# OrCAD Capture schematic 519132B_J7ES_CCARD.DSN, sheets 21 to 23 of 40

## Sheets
21 21.POWER LM5176: size C; rev: A
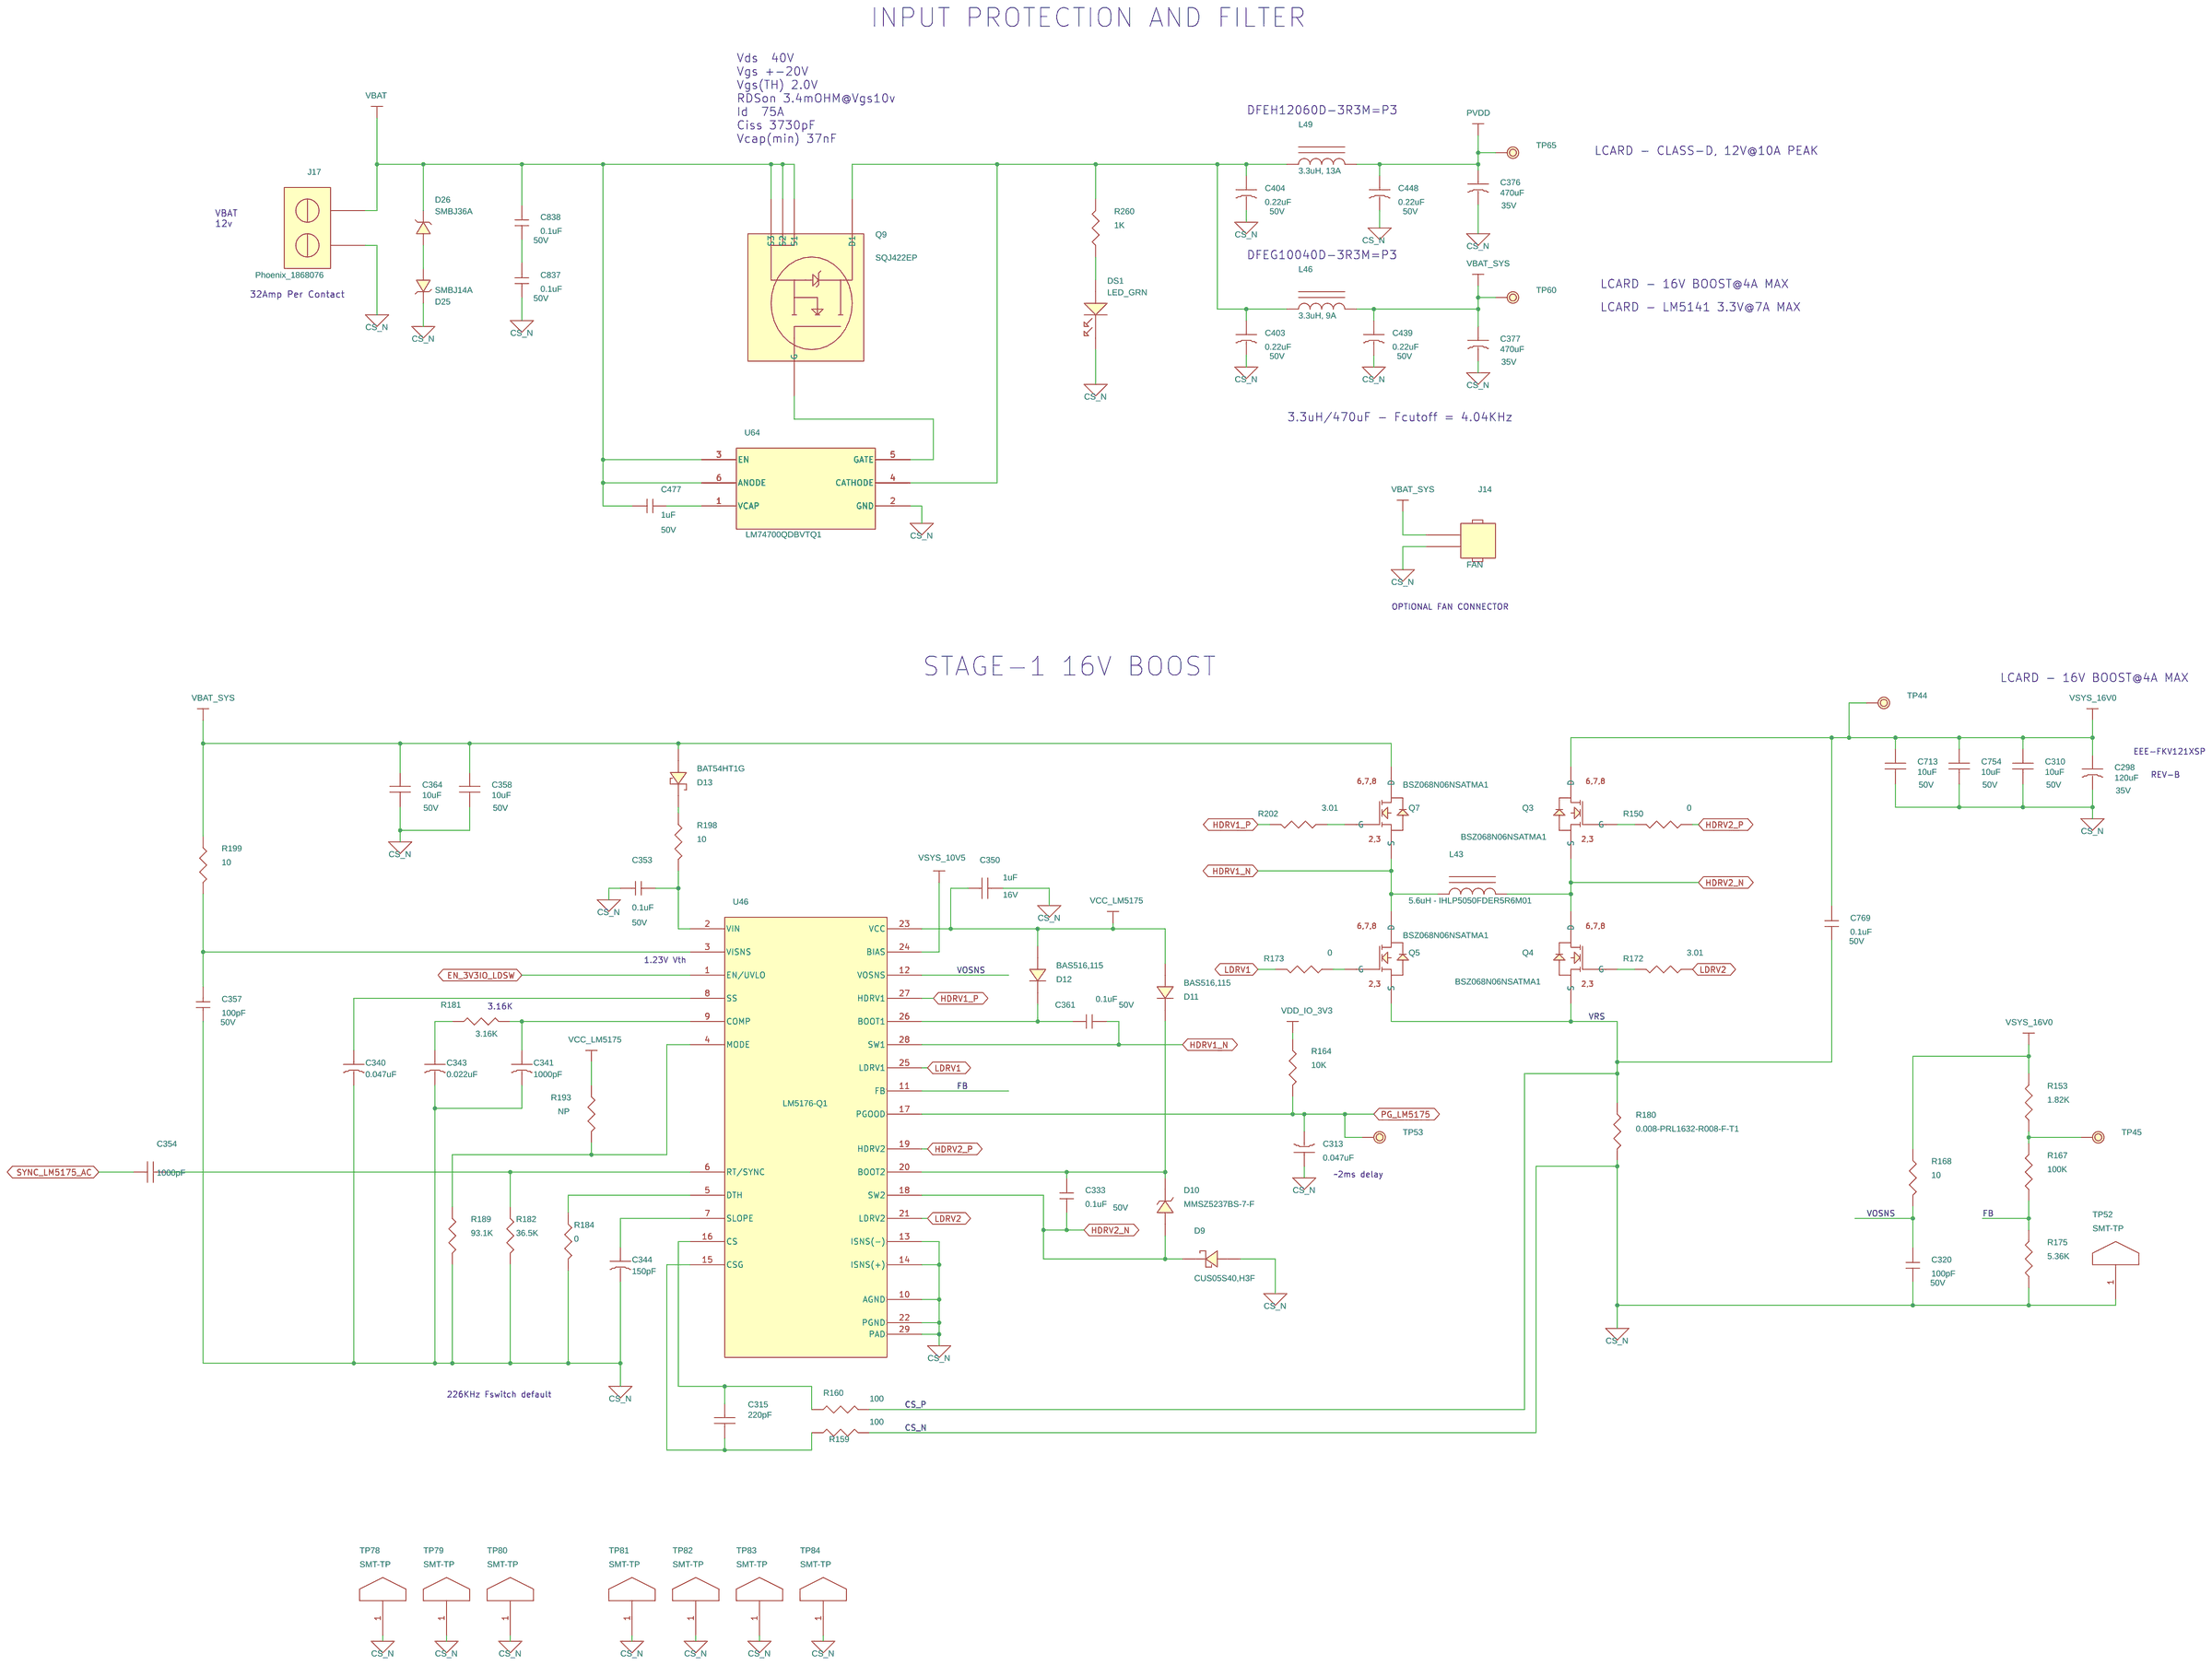
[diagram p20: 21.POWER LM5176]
22 22.POWER LM5141: size C; rev: A
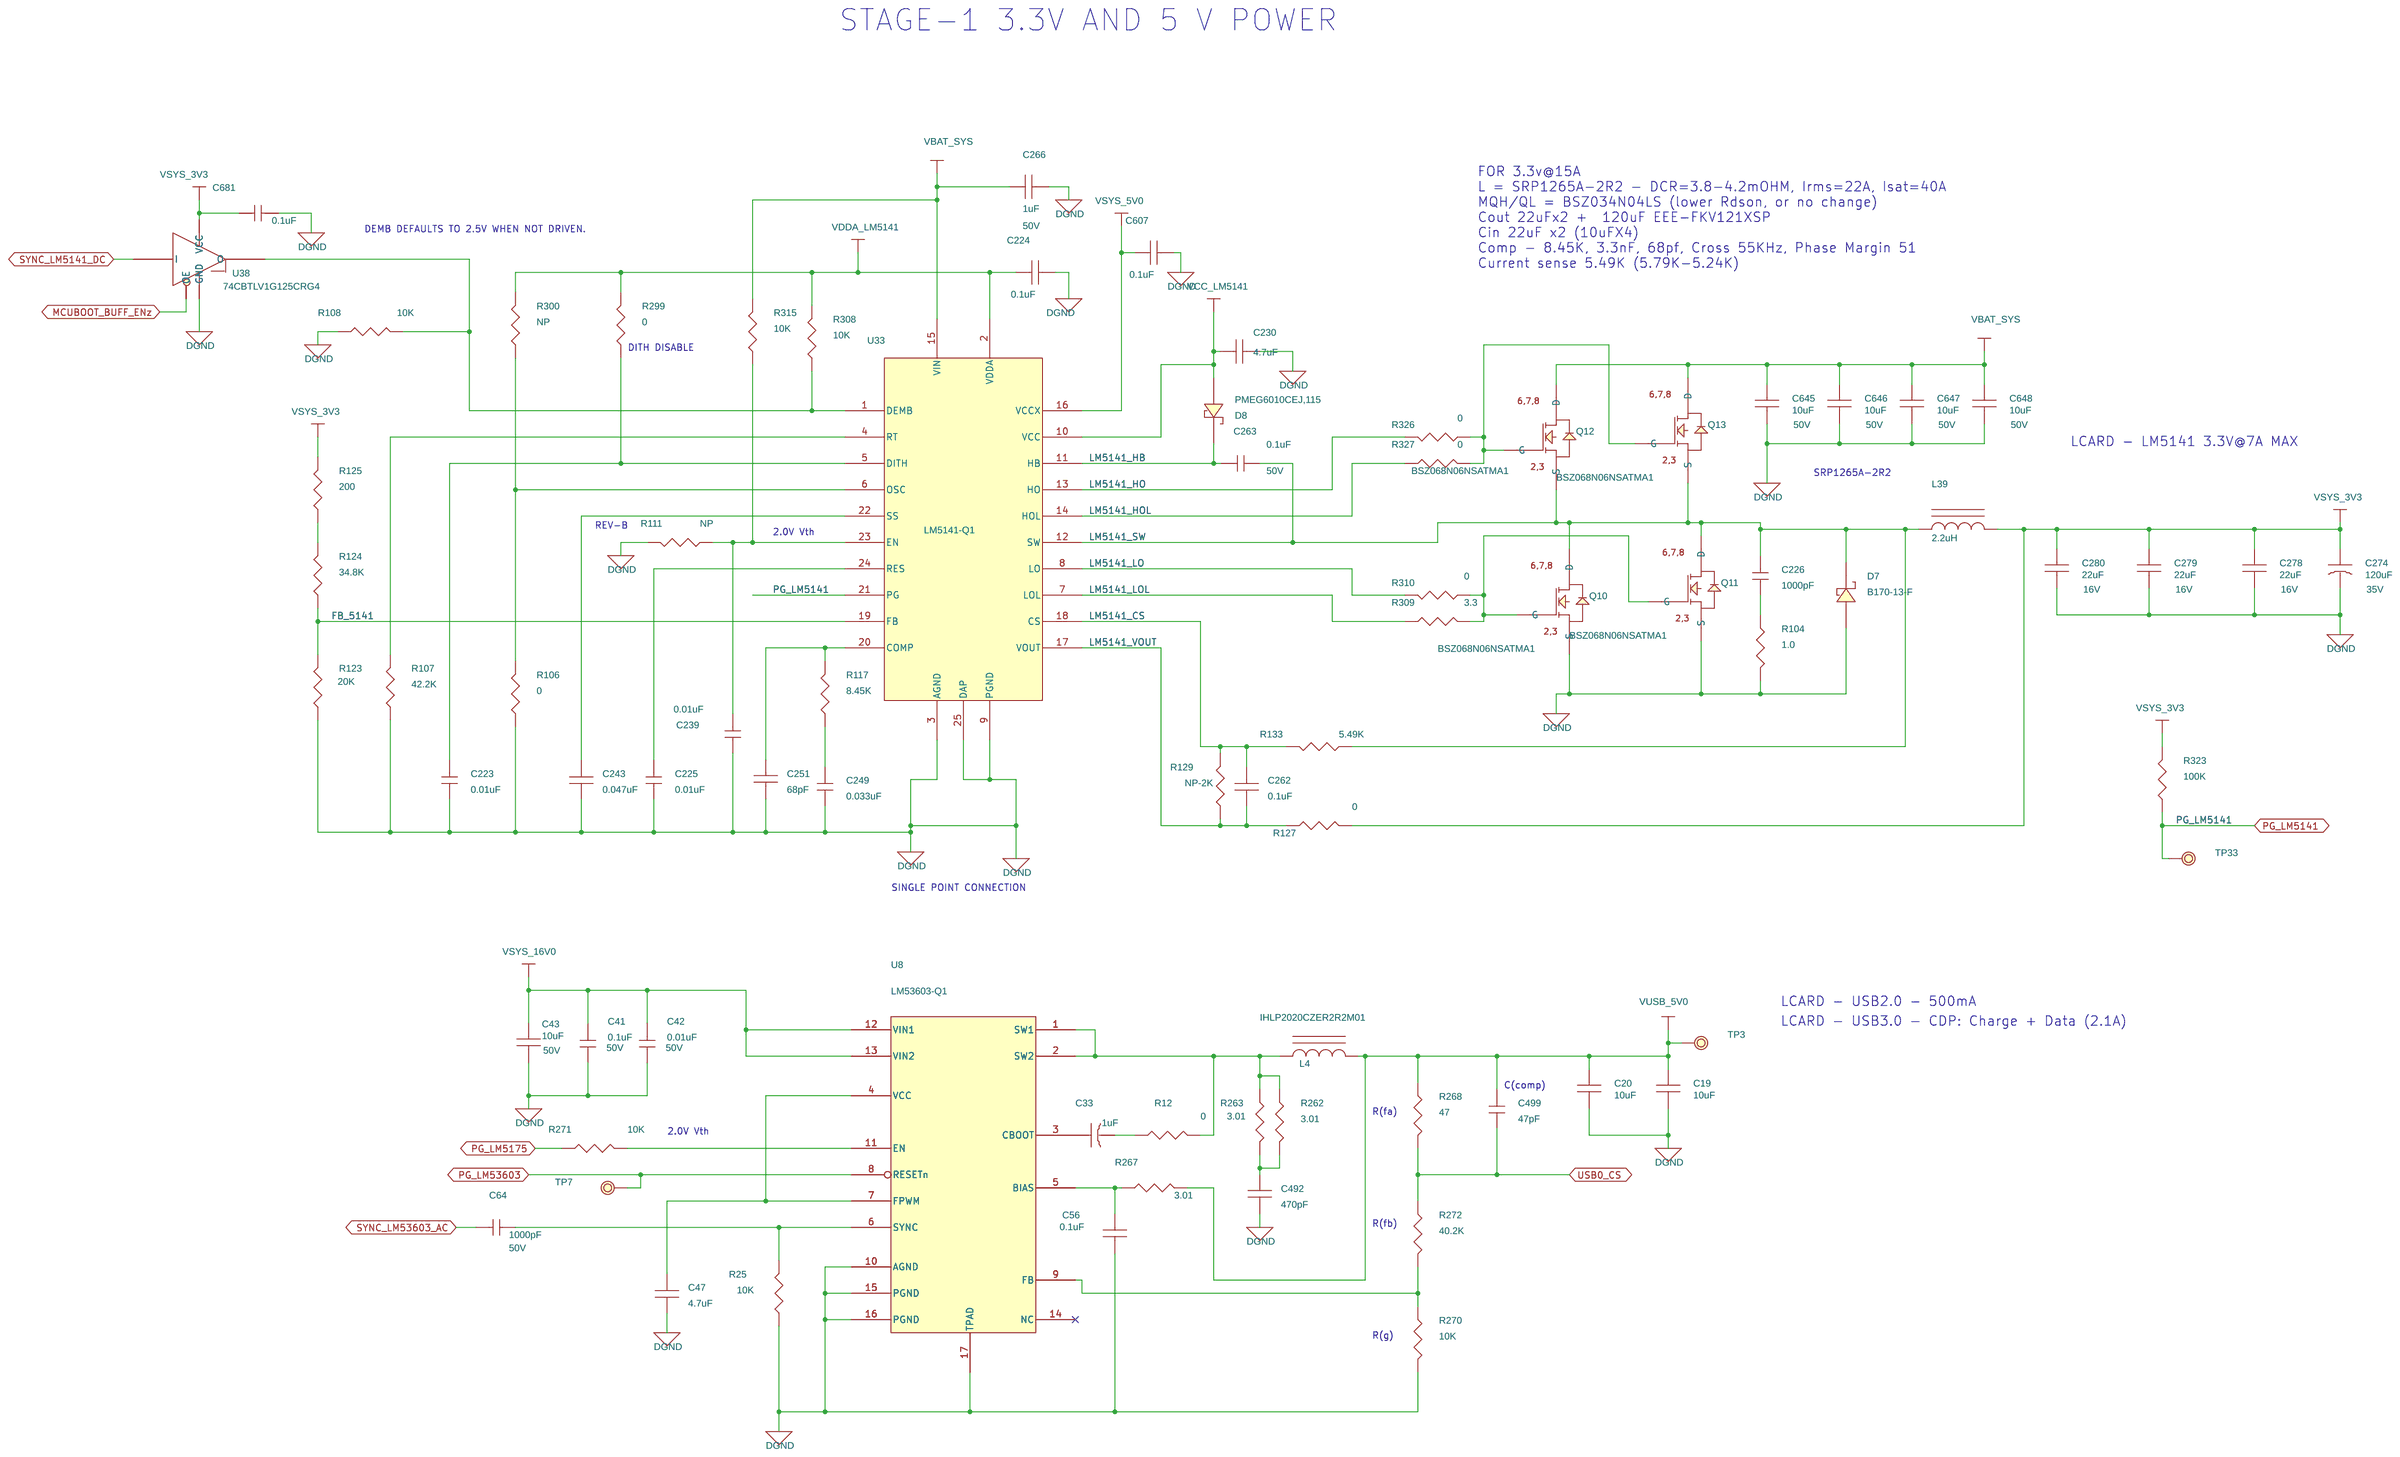
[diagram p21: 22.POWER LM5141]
23 23. PMIC A: size C; rev: A
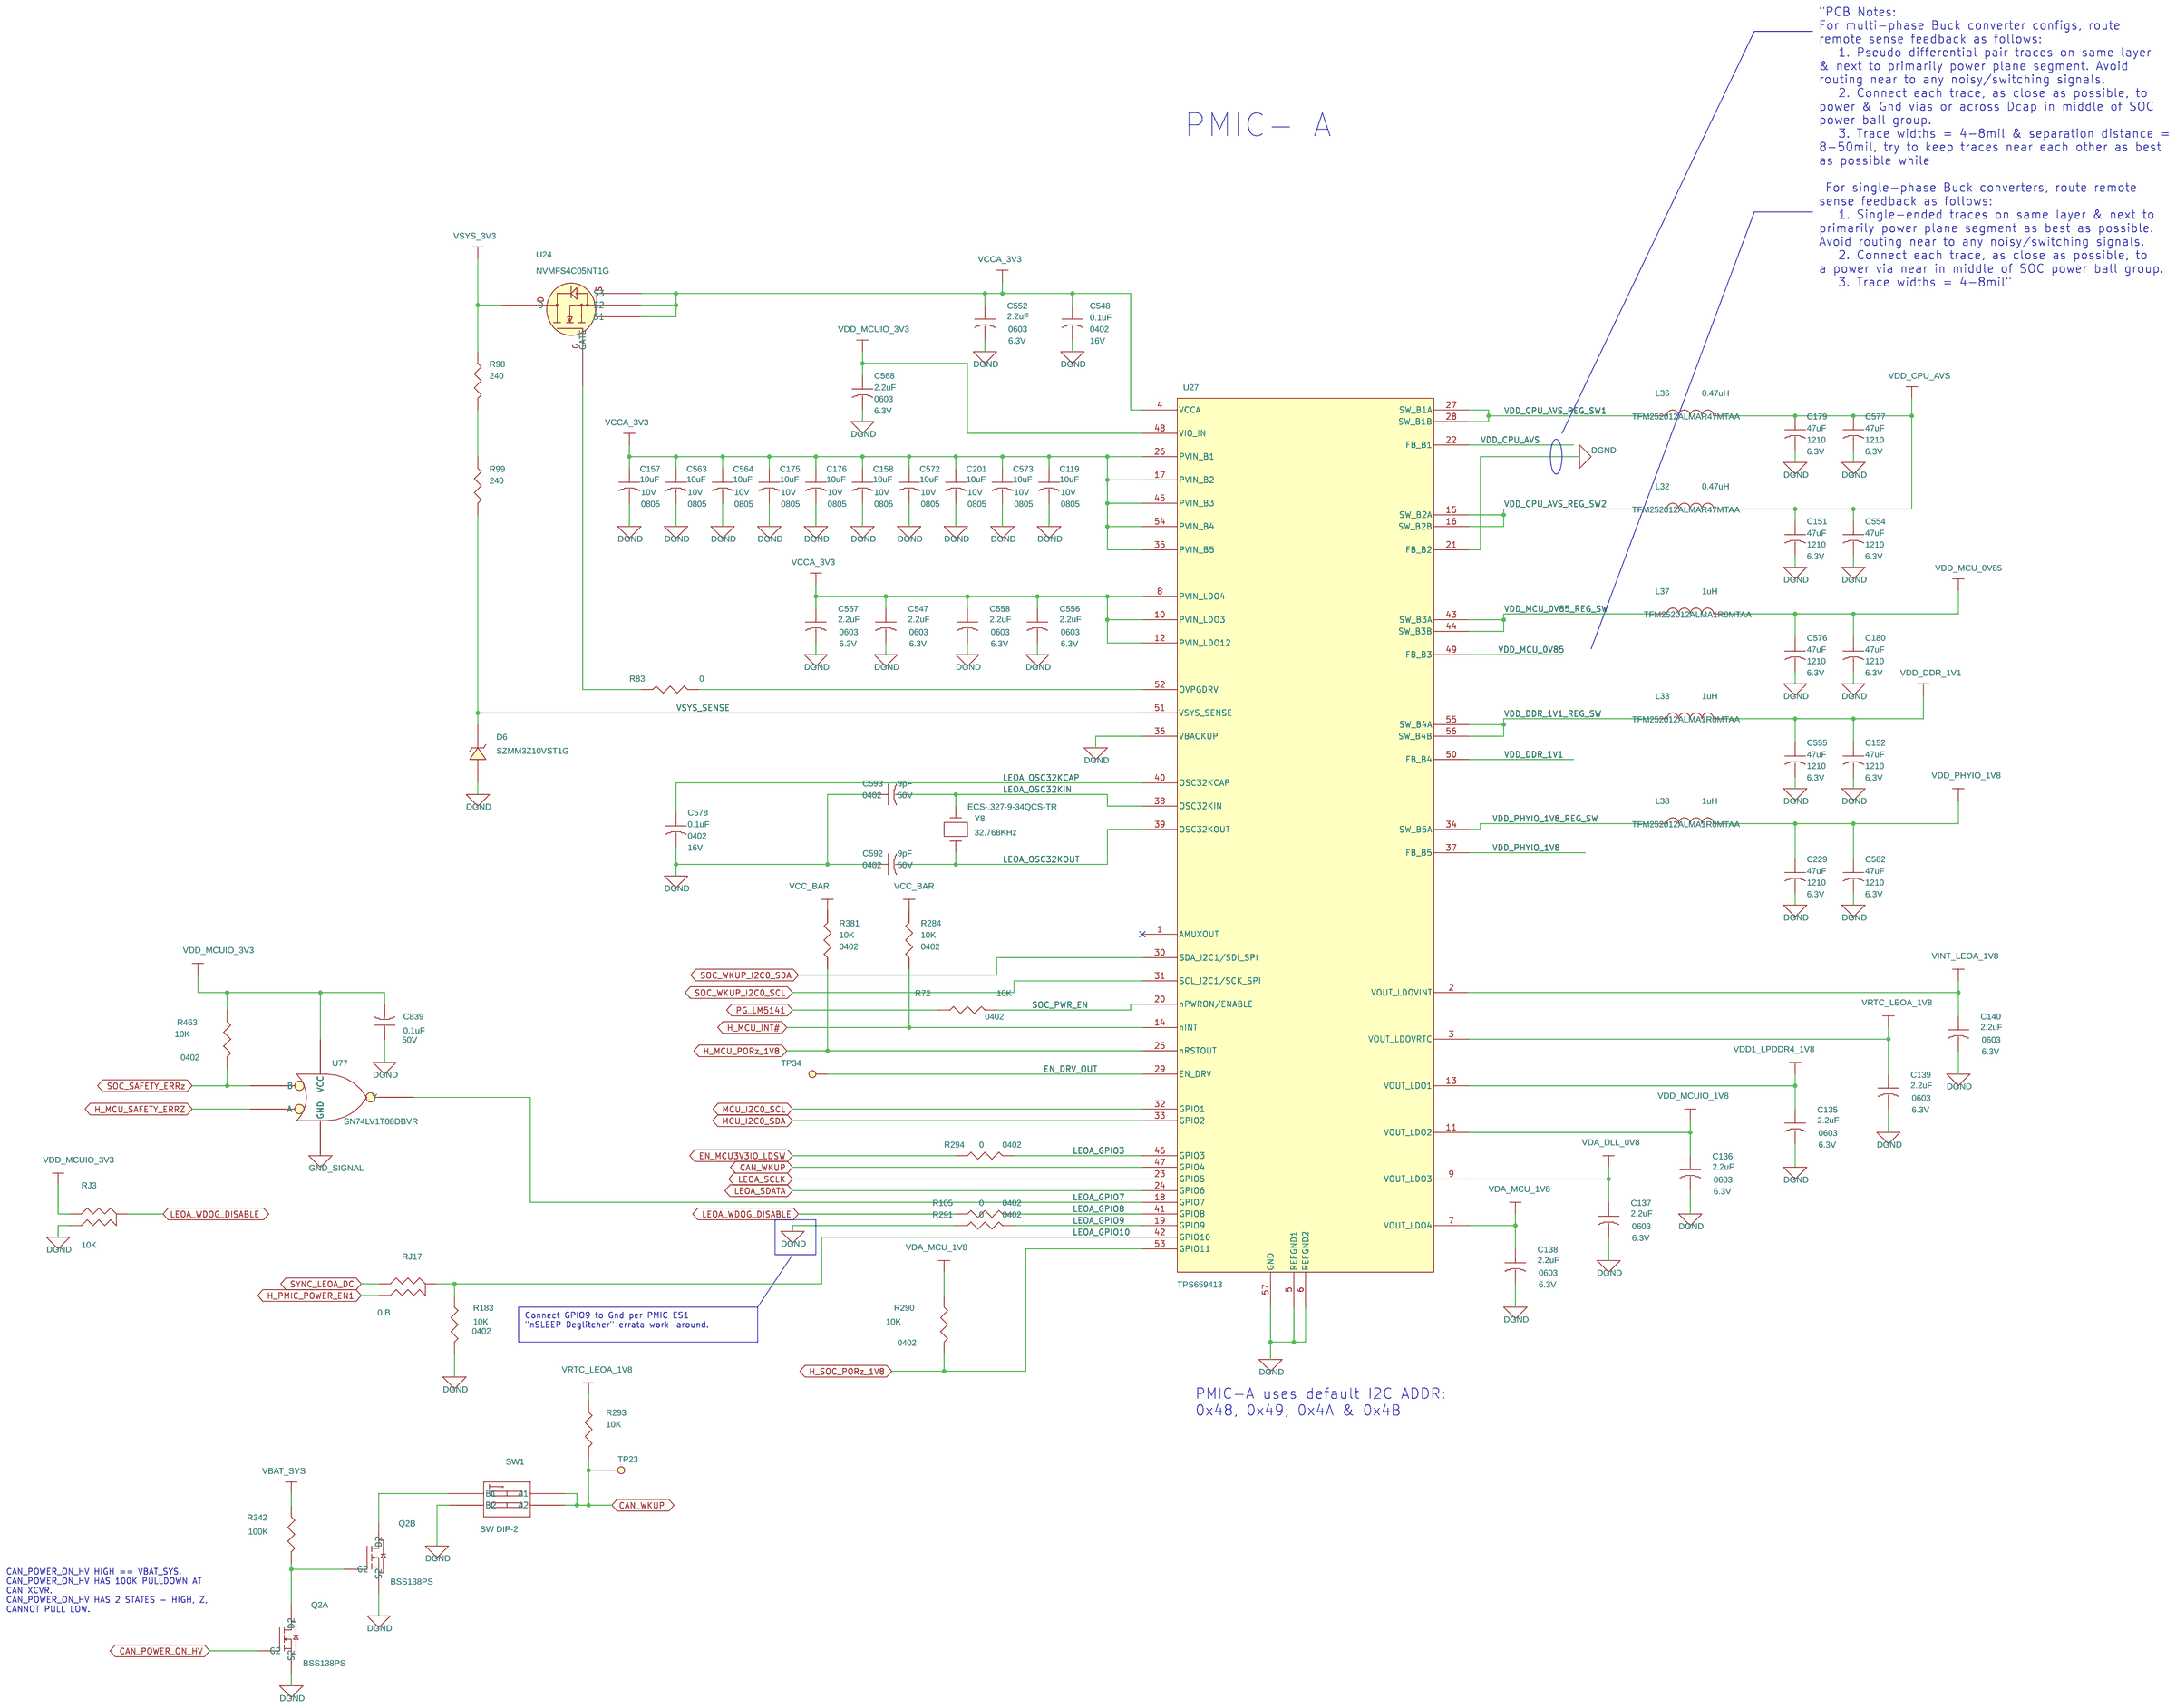
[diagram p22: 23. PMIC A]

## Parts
sheet 21.POWER LM5176
C298  120uF  [cap-fk-d8-65x117]
C310  10uF  [c1210-70x102]
C313  0.047uF  [c402-25rd]
C315  220pF  [c402-25]
C320  100pF  [c402-25]
C333  0.1uF  [c603-35x45]
C340  0.047uF  [c402-25]
C341  1000pF  [c402-25]
C343  0.022uF  [c402-25]
C344  150pF  [c402-25]
C350  1uF  [c603-35x45]
C353  0.1uF  [c603-35x45]
C354  1000pF  [c402-25]
C357  100pF  [c402-25]
C358  10uF  [c1210-70x102]
C361  0.1uF  [c603-35x45]
C364  10uF  [c1210-70x102]
C376  470uF  [cap-elec-h13]
C377  470uF  [cap-elec-h13]
C403  0.22uF  [c603-35x45]
C404  0.22uF  [c603-35x45]
C439  0.22uF  [c603-35x45]
C448  0.22uF  [c603-35x45]
C477  1uF  [c805-35x60]
C713  10uF  [c1210-70x102]
C754  10uF  [c1210-70x102]
C769  0.1uF  [c603-35x45]
C837  0.1uF  [c603-35x45]
C838  0.1uF  [c603-35x45]
D9  CUS05S40,H3F  [sod323]
D10  MMSZ5237BS-7-F  [sod323]
D11  BAS516,115  [SOD523]
D12  BAS516,115  [SOD523]
D13  BAT54HT1G  [sod323]
D25  SMBJ14A  [smb-uni]
D26  SMBJ36A  [smb-uni]
DS1  LED_GRN  [led1206-59x59]
J14  FAN  [CON2-200-250]
J17  Phoenix_1868076  [Phoenix_1868076]
L43  5.6uH - IHLP5050FDER5R6M01  [ind-ihlp5050]
L46  3.3uH, 9A  [ind-dfeg10040]
L49  3.3uH, 13A  [ind-dfeh12060]
Q3  BSZ068N06NSATMA1  [tsdson8]
Q4  BSZ068N06NSATMA1  [tsdson8]
Q5  BSZ068N06NSATMA1  [tsdson8]
Q7  BSZ068N06NSATMA1  [tsdson8]
Q9  SQJ422EP  [pwr-q5a-slps319]
R150  0  [r402-25]
R153  1.82K  [r603-35x45]
R159  100  [r402-25]
R160  100  [r402-25]
R164  10K  [r402-25]
R167  100K  [r402-25]
R168  10  [r402-25]
R172  3.01  [r402-25]
R173  0  [r402-25]
R175  5.36K  [r603-35x45]
R180  0.008-PRL1632-R008-F-T1  [r0612]
R181  3.16K  [r603-35x45]
R182  36.5K  [r402-25]
R184  0  [r402-25]
R189  93.1K  [r402-25]
R193  NP  [r402-25]
R198  10  [r402-25]
R199  10  [r402-25]
R202  3.01  [r402-25]
R260  1K  [r402-25]
TP44  TP  [tp-30RD13]
TP45  TP  [tp-30RD13]
TP52  SMT-TP  [TP1-70X135]
TP53  TP  [tp-30RD13]
TP60  TP  [tp-30RD13]
TP65  TP  [tp-30RD13]
TP78  SMT-TP  [TP1-70X135]
TP79  SMT-TP  [TP1-70X135]
TP80  SMT-TP  [TP1-70X135]
TP81  SMT-TP  [TP1-70X135]
TP82  SMT-TP  [TP1-70X135]
TP83  SMT-TP  [TP1-70X135]
TP84  SMT-TP  [TP1-70X135]
U46  LM5176-Q1  [PWP28-14X70]
U64  LM74700QDBVTQ1  [dbv6-27x39-6]
sheet 22.POWER LM5141
C19  10uF  [C1206-40X70]
C20  10uF  [C1206-40X70]
C33  1uF  [c603-35x45]
C41  0.1uF  [c603-35x45]
C42  0.01uF  [c402-25]
C43  10uF  [c1210-70x102]
C47  4.7uF  [c805-35x60]
C56  0.1uF  [c402-25rd]
C64  1000pF  [c402-25]
C223  0.01uF  [c402-25]
C224  0.1uF  [c402-25]
C225  0.01uF  [c402-25]
C226  1000pF  [c402-25]
C230  4.7uF  [C805-35X60]
C239  0.01uF  [c402-25]
C243  0.047uF  [c402-25]
C249  0.033uF  [c402-25]
C251  68pF  [c402-25]
C262  0.1uF  [c402-25]
C263  0.1uF  [c603-35x45]
C266  1uF  [c805-35x60]
C274  120uF  [cap-fk-d8-65x117]
C278  22uF  [c1210-70x102]
C279  22uF  [c1210-70x102]
C280  22uF  [c1210-70x102]
C492  470pF  [c402-25]
C499  47pF  [c402-25]
C607  0.1uF  [c402-25]
C645  10uF  [c1210-70x102]
C646  10uF  [c1210-70x102]
C647  10uF  [c1210-70x102]
C648  10uF  [c1210-70x102]
C681  0.1uF  [c402-25]
D7  B170-13-F  [sma2-78sq]
D8  PMEG6010CEJ,115  [sod323]
L4  IHLP2020CZER2R2M01  [ind-ihlp2020]
L39  2.2uH  [IND_SRP1265A]
Q10  BSZ068N06NSATMA1  [tsdson8]
Q11  BSZ068N06NSATMA1  [tsdson8]
Q12  BSZ068N06NSATMA1  [tsdson8]
Q13  BSZ068N06NSATMA1  [tsdson8]
R12  0  [r402-25]
R25  10K  [r402-25]
R104  1.0  [r1206-40x70]
R106  0  [r402-25]
R107  42.2K  [r402-25]
R108  10K  [r402-25]
R111  NP  [r402-25]
R117  8.45K  [r402-25]
R123  20K  [r402-25]
R124  34.8K  [r402-25]
R125  200  [r402-25]
R127  0  [r402-25]
R129  NP-2K  [r402-25]
R133  5.49K  [r402-25]
R262  3.01  [r402-25]
R263  3.01  [r402-25]
R267  3.01  [r402-25]
R268  47  [r402-25]
R270  10K  [r402-25]
R271  10K  [r402-25]
R272  40.2K  [r402-25]
R299  0  [r402-25]
R300  NP  [r402-25]
R308  10K  [r402-25]
R309  3.3  [r402-25]
R310  0  [r402-25]
R315  10K  [r402-25]
R323  100K  [r402-25]
R326  0  [r402-25]
R327  0  [r402-25]
TP3  TP  [tp-30RD13]
TP7  TP  [tp-30RD13]
TP33  TP  [tp-30RD13]
U8  LM53603-Q1  [pwp16-14x70-pad]
U33  LM5141-Q1  [rge24-11x28-4mm]
U38  74CBTLV1G125CRG4  [dck-5]
sheet 23. PMIC A
C119  10uF  [CAP0805_1-5]
C135  2.2uF  [CAP0603_1]
C136  2.2uF  [CAP0603_1]
C137  2.2uF  [CAP0603_1]
C138  2.2uF  [CAP0603_1]
C139  2.2uF  [CAP0603_1]
C140  2.2uF  [CAP0603_1]
C151  47uF  [CAP1210_2-75]
C152  47uF  [CAP1210_2-75]
C157  10uF  [CAP0805_1-5]
C158  10uF  [CAP0805_1-5]
C175  10uF  [CAP0805_1-5]
C176  10uF  [CAP0805_1-5]
C179  47uF  [CAP1210_2-75]
C180  47uF  [CAP1210_2-75]
C201  10uF  [CAP0805_1-5]
C229  47uF  [CAP1210_2-75]
C547  2.2uF  [CAP0603_1]
C548  0.1uF  [CAP0402_0-75]
C552  2.2uF  [CAP0603_1]
C554  47uF  [CAP1210_2-75]
C555  47uF  [CAP1210_2-75]
C556  2.2uF  [CAP0603_1]
C557  2.2uF  [CAP0603_1]
C558  2.2uF  [CAP0603_1]
C563  10uF  [CAP0805_1-5]
C564  10uF  [CAP0805_1-5]
C568  2.2uF  [CAP0603_1]
C572  10uF  [CAP0805_1-5]
C573  10uF  [CAP0805_1-5]
C576  47uF  [CAP1210_2-75]
C577  47uF  [CAP1210_2-75]
C578  0.1uF  [CAP0402_0-75]
C582  47uF  [CAP1210_2-75]
C592  9pF  [CAP0402_0-75]
C593  9pF  [CAP0402_0-75]
C839  0.1uF  [c402-25]
D6  SZMM3Z10VST1G  [DIO_SOD323_1-1]
L32  0.47uH  [IND1008_1-2]
L33  1uH  [IND1008_1-2]
L36  0.47uH  [IND1008_1-2]
L37  1uH  [IND1008_1-2]
L38  1uH  [IND1008_1-2]
Q2  BSS138PS  [sot363-16x45]  (sections A,B)
R72  10K  [RES0402_0-5]
R83  0  [RES0402_0-5]
R98  240  [RES0402_0-5]
R99  240  [RES0402_0-5]
R105  0  [RES0402_0-5]
R183  10K  [RES0402_0-5]
R284  10K  [RES0402_0-5]
R290  10K  [RES0402_0-5]
R291  0  [RES0402_0-5]
R293  10K  [r402-25]
R294  0  [RES0402_0-5]
R342  100K  [r402-25]
R381  10K  [RES0402_0-5]
R463  10K  [RES0402_0-5]
RJ3  10K  [JMP402-25]
RJ17  0.B  [JMP402-25]
SW1  SW DIP-2  [sw2-30x50-tda]
TP23  TP_VIA_MEM0  [tp-18RD8]
TP34  TP_VIA_MEM0  [tp-18RD8]
U24  NVMFS4C05NT1G  [DFN5_NTMFS4835N_240X200_1-1]
U27  TPS659413  [VQFN56_19-68_320X320_0-9_EP6]
U77  SN74LV1T08DBVR  [DBV-20X60-5]
Y8  32.768KHz  [XTAL_ECS-32_130X60_SMD_0-9]

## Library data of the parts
C274 C298 = CAP: Part #: 105117-0122R; Voltage: 35V
C43 C310 C358 C364 C645-C648 C713 C754 = CAP_NP_0: Part #: 104665-0101R; Voltage: 50V
C313 C340 = CAP: Part #: 102058-1471R; Voltage: 50V
C315 = CAP_0402_220pf_x7r_50v_10%_X_SD: Part #: 101782-1223R
C320 C357 = CAP_NP: Part #: 101782-1103R; Voltage: 50V
C41 C263 C333 C353 C361 C769 C837 C838 = CAP_NP: Part #: 103885-1100R; Voltage: 50V
C341 = CAP: Part #: 102756-1102R; Voltage: 50V
C343 = CAP: Part #: 102058-1221R; Voltage: 50V
C344 = CAP: Part #: 101782-1153R; Voltage: 50V
C350 = CAP_NP_0: Part #: 104723-0100R; Voltage: 16V
C354 = CAP_AM_0402_0.1uf_x7r_16v_10%_X: Part #: 102058-1102R; Voltage: 50V
C376 C377 = CAP: Part #: 104864-0472R; Voltage: 35V
C403 C404 C439 C448 = CAP: Part #: 103885-1220R; Voltage: 50V
C477 = CAP_NP: Part #: 104866-0100R; Voltage: 50V
D9 = DIODE_SCHOTTKY_0: Part #: 104971-0001R
D10 = DIODE_ZENER: Part #: 104967-0082R
D11 D12 = DIODE: Part #: 104964-0001R
D13 = DIODE_SCHOTTKY_0: Part #: 104963-0001R
D25 = Diode_SMCJ15CA: Part #: 105094-0014R
D26 = Diode_SMCJ15CA: Part #: 105094-0036R
DS1 = LED_RED_0: Part #: 100823-0001R
J14 = HEADER_2: Part #: 100412-0002R
J17 = Phoenix_1868076: Part #: 105311-0002R
L43 = INDUCTOR_IRON: Part #: 104996-0560R
L46 = CHOKE_HASH-IRON: Part #: 104909-0330R
L49 = CHOKE_HASH-IRON: Part #: 105338-0330R
Q3-Q5 Q7 Q10-Q13 = BSZ042N06NS: Part #: 105138-0001R
Q9 = MOSFET_CSD16406Q3_0: Part #: 104999-0001R
R12 R127 R150 R173 R184 R299 R310 R326 R327 = R_2: Part #: 101370-0001R
R153 = R_2: Part #: 100642-1822R
R159 R160 = R_2: Part #: 102145-1001R
R25 R108 R164 R270 R308 R315 = R: Part #: 102145-1003R
R167 = R_2: Part #: 102145-1004R
R168 R198 R199 = R_2: Part #: 102145-1000R
R172 R202 = R_2: Part #: 102145-0301R
R175 = R_2: Part #: 100642-5362R
R180 = R_2: Part #: 104727-0008R
R181 = R_2: Part #: 100642-3162R
R182 = R_2: Part #: 102145-3653R
R189 = R_2: Part #: 102145-9313R
R193 R300 = R_2: Part #: R0402-NOPOP
R260 = R_2: Part #: 102145-1002R
TP3 TP7 TP33 TP44 TP45 TP53 TP60 TP65 = TP-30RD13: Part #: TP-30RD13-NO-POP
TP52 TP78-TP84 = SMT-TP: Part #: 104178-0001R
U46 = LM5175-Q1: Part #: 105348-0001R
U64 = LM74700QDBVTQ1: Part #: 105281-0001R
C19 C20 = CAP_NP_0: Part #: 104724-0101R; Voltage: 25V
C33 = CAP: Part #: 104723-0100R; Voltage: 16V
C42 C223 C225 C239 = CAP_NP: Part #: 104725-1101R; Voltage: 50V
C47 = CAP_AM_0402_0.1uf_x7r_16v_10%_X: Part #: 104719-0470R
C56 = CAP_AM_0402_0.1uf_x7r_16v_10%_X: Part #: 104446-1100R
C64 C226 = CAP_NP: Part #: 102058-1102R; Voltage: 50V
C224 C262 C607 = CAP_NP_2: Part #: 104446-1100R; Voltage: 16V
C230 = CAP_NP_2: Part #: 101063-0470R; Voltage: 16V
C243 = CAP_NP_2: Part #: 102058-1471R; Voltage: 50V
C249 = CAP_NP: Part #: 102058-1331R; Voltage: 50V
C251 = CAP_NP_3: Alternate_mfr_part_number_B: 102366-1685R; Part #: 101782-1684R
C266 = CAP_NP_0: Part #: 104866-0100R; Voltage: 50V
C278-C280 = CAP_NP_0: MANUFACTURER: TDK; MANUF_PN: CGA6P1X7R1C226M250AC; Part #: 105112-0221R; RATING: 16V; SIZE: 1210; TOL: 20%; Voltage: 16V
C492 = CAP_NP_3: Alternate_mfr_part_number_B: 102366-1685R; Part #: 104945-1473R
C499 = CAP_NP: Part #: 101782-1474R; Voltage: 50V
C681 = CAP_NP: Part #: 104446-1100R; RATING: 16V; Voltage: 16V
D7 = DIODE_SCHOTTKY_0: Part #: 104729-0001R
D8 = DIODE_SCHOTTKY_0: Part #: 104970-0001R
L4 = INDUCTOR_IRON: Part #: 104989-0220R
L39 = INDUCTOR_IRON: Part #: 105336-0220R
R104 = R_2: Part #: 100232-0100R
R106 = R: Part #: 101370-0001R
R107 = R: Part #: 102145-4223R
R111 R129 = R: Part #: R0402-NOPOP
R117 = R: Part #: 102145-8452R
R123 = R: Part #: 102145-2003R
R124 = R: Part #: 102145-3483R
R125 = R: Part #: 102145-2001R
R133 = R: Part #: 102145-5492R
R262 R263 R267 = R: Part #: 102145-0301R
R268 = R: Part #: 102145-4700R
R271 = R_2: Part #: 102145-1003R
R272 = R: Part #: 102145-4023R
R309 = R_2: Part #: 101370-0330R
R323 R342 = R: Part #: 102145-1004R
U8 = LM53603-Q1: Part #: 104968-0001R
U33 = LM5141-Q1: Part #: 104965-0001R
U38 = SN74LVC1G125_0: Part #: 101689-0125R
C119 C157 C158 C175 C176 C201 C563 C564 C572 C573 = CAP: CAP CERAMIC 10uF 10V 10% X7R AUTO 0805; Chkd/date: MANIRAJA/080419; Crtd /date: ALVY/050419; Custom_Duty: 15%; Customs_HS_Code: 85322990; Distributor_name: DIGIKEY; Distributor_part_number: 490-14531-1-ND; Footprint Path: Y:\MIS_DATABASE\Library\ALTIUM_TOOL\PCB_FOOTPRINTS\Altium_Footprint_Lib.PcbLib; Footprint Ref: c805-35x60; Height: 1.40MM; Library Path: Y:\MIS_DATABASE\Library\ALTIUM_TOOL\SCHEMATICS_PARTS\MS_DISCRETE_Library.schlib; MECHANICAL 3D STEP FILE: c805-35x60; Mfr_name: MURATA; Mfr_part_number: GCM21BR71A106KE22K; Mistral Part No: 120019040010-R; Package: 0805; Part #: 104720-0101R; Part_type: CAPACITORS\CERAMIC; Project: J7ES_SOM_DUAL-LEO_PMIC; RoHS: RoHS; Temperature: -55°C+125°C; Tolerance: 10%; Voltage: 10V; Wattage: NA; Weight: 9.5mg; Datasheet: Y:\MIS_DATABASE\DATASHEETS\CAPACITORS\GCM21BR71A106KE22.PDF
C135-C140 C547 C552 C556-C558 C568 = CAP: CAP CERAMIC 2.2uF 6.3V 10% X7R AUTO 0603; Chkd/date: MANIRAJA/050419; Crtd /date: ALVY/050419; Custom_Duty: 15%; Customs_HS_Code: 85322990; Distributor_name: DIGIKEY; Distributor_part_number: 490-5316-1-ND; Footprint Path: Y:\MIS_DATABASE\Library\ALTIUM_TOOL\PCB_FOOTPRINTS\Altium_Footprint_Lib.PcbLib; Footprint Ref: c603-35x45; Height: 0.90MM; Library Path: Y:\MIS_DATABASE\Library\ALTIUM_TOOL\SCHEMATICS_PARTS\MS_DISCRETE_Library.schlib; MECHANICAL 3D STEP FILE: c603-35x45; Mfr_name: MURATA; Mfr_part_number: GCM188R70J225KE22D; Mistral Part No: 120019040009-R; Package: 0603; Part #: 104448-0220R; Part_type: CAPACITORS\CERAMIC; Project: J7ES_SOM_DUAL-LEO_PMIC; RoHS: RoHS; Temperature: -55°C+125°C; Tolerance: 10%; Voltage: 6.3V; Wattage: NA; Weight: 6.3mg; Datasheet: Y:\MIS_DATABASE\DATASHEETS\CAPACITORS\GCM188R70J225KE22.PDF
C151 C152 C179 C180 C229 C554 C555 C576 C577 C582 = CAP: CAP CERAMIC 47uF 6.3V 10% X7R AUTO 1210; Chkd/date: MANIRAJA/280918; Crtd /date: ALVY/280918; Custom_Duty: 15%; Customs_HS_Code: 85322990; Distributor_name: DIGIKEY; Distributor_part_number: 490-4844-1-ND; Footprint Path: Y:\MIS_DATABASE\Library\ALTIUM_TOOL\PCB_FOOTPRINTS\Altium_Footprint_Lib.PcbLib; Footprint Ref: c1210-70x102; Height: 2.70MM; Library Path: Y:\MIS_DATABASE\Library\ALTIUM_TOOL\SCHEMATICS_PARTS\MS_DISCRETE_Library.schlib; MECHANICAL 3D STEP FILE: c1210-70x102; Mfr_name: MURATA; Mfr_part_number: GCM32ER70J476KE19L; Mistral Part No: 120018090056-R; Package: 1210; Part #: 104955-0471R; Part_type: CAPACITORS\CERAMIC; Project: TI_J7_SVB-DUT; RoHS: RoHS; Temperature: -55°C+125°C; Tolerance: 10%; Voltage: 6.3V; Wattage: NA; Weight: 110mg; Datasheet: Y:\MIS_DATABASE\DATASHEETS\CAPACITORS\MURATA-GCM-SER.PDF
C548 C578 = CAP: CAP CERAMIC 0.1uF 16V 10% X7R AUTO 0402; Chkd/date: NAVEED/021014; Crtd /date: VASANTHA/300514; Custom_Duty: 15%; Customs_HS_Code: 85322990; Distributor_name: DIGIKEY; Distributor_part_number: 490-4759-1-ND; Footprint Path: Y:\MIS_DATABASE\Library\ALTIUM_TOOL\PCB_FOOTPRINTS\Altium_Footprint_Lib.PcbLib; Footprint Ref: c402-25; Height: 0.55MM; Library Path: Y:\MIS_DATABASE\Library\ALTIUM_TOOL\SCHEMATICS_PARTS\MS_DISCRETE_Library.schlib; MECHANICAL 3D STEP FILE: c402-25; Mfr_name: MURATA; Mfr_part_number: GCM155R71C104KA55D; Mistral Part No: 120016070006-R; Package: 0402; Part #: 104446-1100R; Part_type: CAPACITORS\CERAMIC; Project: DCMIST_FPGA_CARD; RoHS: RoHS; Temperature: -55°C+125°C; Tolerance: 10%; Voltage: 16V; Wattage: NA; Weight: 6mg; Datasheet: Y:\MIS_DATABASE\DATASHEETS\CAPACITORS\MURATA-GCM-SER.PDF
C592 C593 = CAP: CAP CERAMIC 9pF 50V 0.5pF% C0G(NP0) AUTO 0402; Chkd/date: VASANTHA/090419; Crtd /date: ALVY/090419; Custom_Duty: 15%; Customs_HS_Code: 85322990; Distributor_name: DIGIKEY; Distributor_part_number: 445-12155-1-ND; Footprint Path: Y:\MIS_DATABASE\Library\ALTIUM_TOOL\PCB_FOOTPRINTS\Altium_Footprint_Lib.PcbLib; Footprint Ref: c402-25; Height: 0.55MM; Library Path: Y:\MIS_DATABASE\Library\ALTIUM_TOOL\SCHEMATICS_PARTS\MS_DISCRETE_Library.schlib; MECHANICAL 3D STEP FILE: c402-25; Mfr_name: TDK CORPORATION; Mfr_part_number: CGA2B2NP01H090D050BA; Mistral Part No: 120019040066-R; Package: 0402; Part #: 105319-1094R; Part_type: CAPACITORS\CERAMIC; Project: J7ES_SOM_DUAL-LEO_PMIC; RoHS: RoHS; Temperature: -55°C+150°C; Tolerance: 0.5pF%; Voltage: 50V; Wattage: NA; Weight: 0.65mg; Datasheet: Y:\MIS_DATABASE\DATASHEETS\CAPACITORS\CGA2B2NP01H090D050BA.PDF
C839 = CAP: CAP CERAMIC 0.1uF 50V 10% X7R 0402; Chkd/date: MANIRAJA/230418; Crtd /date: ALVY/230418; Custom_Duty: 15%; Customs_HS_Code: 85322990; Distributor_name: DIGIKEY; Distributor_part_number: 587-3498-1-ND; Footprint Path: Y:\MIS_DATABASE\Library\ALTIUM_TOOL\PCB_FOOTPRINTS\Altium_Footprint_Lib.PcbLib; Height: 0.55MM; Library Path: Y:\MIS_DATABASE\Library\ALTIUM_TOOL\SCHEMATICS_PARTS\MS_DISCRETE_Library.schlib; Mfr_name: TAIYO YUDEN; Mfr_part_number: UMK105B7104KV-FR; Mistral Part No: 120011100014-R; Package: 0402; Part #: 104910-1100R; Part_type: CAPACITORS\CERAMIC; Project: GC150_PHASE-II_AB; RoHS: RoHS; Temperature: -55°C+125°C; Tolerance: 10%; Voltage: 50V; Wattage: NA; Weight: 0.65mg; Datasheet: Y:\MIS_DATABASE\DATASHEETS\CAPACITORS\UMK105B7104KV-FR.PDF
D6 = DIODE_ZENER: DIODE ZENER 10V 300mW SOD323; Chkd/date: MANIRAJA/170419; Crtd /date: MANIRAJA/170419; Custom_Duty: 15%; Customs_HS_Code: 85412900; Distributor_name: DIGIKEY; Distributor_part_number: SZMM3Z10VST1GOSCT-ND; Footprint Path: Y:\MIS_DATABASE\Library\ALTIUM_TOOL\PCB_FOOTPRINTS\Altium_Footprint_Lib.PcbLib; Height: 1.10MM; Library Path: Y:\MIS_DATABASE\Library\ALTIUM_TOOL\SCHEMATICS_PARTS\MS_DISCRETE_Library.schlib; Mfr_name: ON SEMICONDUCTOR; Mistral Part No: 130019040011-R; Package: SOD323; Part #: 105322-0001R; Part_type: DIODE\ZENER; Project: J7ES_SOM_DUAL-LEO_PMIC; RoHS: RoHS; Temperature: -65°C+150°C; Tolerance: NA; Voltage: 10V; Wattage: NA; Weight: NA; Datasheet: Y:\MIS_DATABASE\DATASHEETS\DISCRETES\DIODES\SZMM3ZXXXST1G.PDF
L32 L36 = INDUCTOR: IND POWER 0.47uH 20% 4.9A 1008; Chkd/date: VASANTHA/010419; Crtd /date: ALVY/010419; Custom_Duty: 24%; Customs_HS_Code: 85437099; Distributor_name: DIGIKEY; Distributor_part_number: 445-181489-1-ND; Footprint Path: Y:\MIS_DATABASE\Library\ALTIUM_TOOL\PCB_FOOTPRINTS\Altium_Footprint_Lib.PcbLib; Height: 1.20MM; Library Path: Y:\MIS_DATABASE\Library\ALTIUM_TOOL\SCHEMATICS_PARTS\MS_DISCRETE_Library.schlib; Mfr_name: TDK CORPORATION; Mfr_part_number: TFM252012ALMAR47MTAA; Mistral Part No: 130019040001-R; Package: 1008; Part #: 105324-1470R; Project: J7ES_SOM_DUAL-LEO_PMIC; RoHS: RoHS; Temperature: -55°C+150°C; Tolerance: 20%; Voltage: NA; Wattage: NA; Weight: NA; Datasheet: Y:\MIS_DATABASE\DATASHEETS\DISCRETES\INDUCTORS\TFM252012ALMA-SER.PDF
L33 L37 L38 = INDUCTOR: IND POWER 1uH 3.7A 20% AUTO 1008; Chkd/date: MANIRAJA/160419; Crtd /date: MANIRAJA/160419; Custom_Duty: 24%; Customs_HS_Code: 85437099; Distributor_name: DIGIKEY; Distributor_part_number: 445-175183-1-ND; Footprint Path: Y:\MIS_DATABASE\Library\ALTIUM_TOOL\PCB_FOOTPRINTS\Altium_Footprint_Lib.PcbLib; Height: 1.20MM; Library Path: Y:\MIS_DATABASE\Library\ALTIUM_TOOL\SCHEMATICS_PARTS\MS_DISCRETE_Library.schlib; Mfr_name: TDK CORPORATION; Mfr_part_number: TFM252012ALMA1R0MTAA; Mistral Part No: 130019040010-R; Package: 1008; Part #: 105324-0100R; Project: J7ES_SOM_DUAL-LEO_PMIC; RoHS: RoHS; Temperature: -55°C+150°C; Tolerance: 20%; Voltage: NA; Wattage: NA; Weight: 35mg; Datasheet: Y:\MIS_DATABASE\DATASHEETS\DISCRETES\INDUCTORS\TFM252012ALMA-SER.PDF
Q2 = BSS138PS: Part #: 104958-0001R
R72 R284 R290 R381 R463 = RESISTOR: RES 10K 1/16W 1% 0402; Chkd/date: VASANTHA/201216; Crtd /date: GEETHA/290506; Custom_Duty: 15%; Customs_HS_Code: 85332119; Distributor_name: DIGIKEY; Distributor_part_number: 311-10.0KLRTR-ND; Footprint Path: Y:\MIS_DATABASE\Library\ALTIUM_TOOL\PCB_FOOTPRINTS\Altium_Footprint_Lib.PcbLib; Footprint Ref: r402-25; Height: 0.40MM; Library Path: Y:\MIS_DATABASE\Library\ALTIUM_TOOL\SCHEMATICS_PARTS\MS_DISCRETE_Library.schlib; MECHANICAL 3D STEP FILE: r402-25; Mfr_name: YAGEO AMERICA; Mfr_part_number: RC0402FR-0710KL; Mistral Part No: 110015090015-R; Package: 0402; Part #: 102145-1003R; Part_type: RESISTORS\FIXED; Project: VOCERA; RoHS: RoHS; Temperature: -55°C+155°C; Tolerance: 1%; Voltage: NA; Wattage: 1/16W; Weight: 0.65mg; Datasheet: Y:\MIS_DATABASE\DATASHEETS\RESISTORS\RCXXXXL-SER_MAR18.PDF
R83 R105 R291 R294 = RESISTOR: RES 0E 1/10W JUMPER 0402; Chkd/date: VASANTHA/061216; Crtd /date: NAVEED/201014; Custom_Duty: 15%; Customs_HS_Code: 85332119; Distributor_name: DIGIKEY; Distributor_part_number: P0.0JCT-ND; Footprint Path: Y:\MIS_DATABASE\Library\ALTIUM_TOOL\PCB_FOOTPRINTS\Altium_Footprint_Lib.PcbLib; Footprint Ref: r402-25; Height: 0.40MM; IBISSP_MODLES: VALUE REPEATING 2 TIME; Library Path: Y:\MIS_DATABASE\Library\ALTIUM_TOOL\SCHEMATICS_PARTS\MS_DISCRETE_Library.schlib; MECHANICAL 3D STEP FILE: r402-25; Mfr_name: PANASONIC-ECG; Mfr_part_number: ERJ-2GE0R00X; Mistral Part No: 110018030052-R; Package: 0402; Part #: 101370-0001R; Part_type: RESISTORS\FIXED; Project: AEGIS POM; RoHS: RoHS; Temperature: -55°C+155°C; Tolerance: NA; Voltage: NA; Wattage: 1/10W; Weight: 0.8mg; Datasheet: Y:\MIS_DATABASE\DATASHEETS\RESISTORS\PAN-ERJSER_NOV17.PDF
R98 R99 = RESISTOR: RES 240E 1/16W 5% 0402; Chkd/date: VASANTHA/060117; Crtd /date: GEETHA/070606; Custom_Duty: 15%; Customs_HS_Code: 85332119; Distributor_name: DIGIKEY; Distributor_part_number: 311-240JRCT-ND; Footprint Path: Y:\MIS_DATABASE\Library\ALTIUM_TOOL\PCB_FOOTPRINTS\Altium_Footprint_Lib.PcbLib; Footprint Ref: r402-25; Height: 0.40MM; Library Path: Y:\MIS_DATABASE\Library\ALTIUM_TOOL\SCHEMATICS_PARTS\MS_DISCRETE_Library.schlib; MECHANICAL 3D STEP FILE: r402-25; Mfr_name: YAGEO AMERICA; Mfr_part_number: RC0402JR-07240RL; Mistral Part No: 110009030544-R; Package: 0402; Part #: 102145-2401R; Part_type: RESISTORS\FIXED; Project: VOCERA; RoHS: RoHS; Temperature: -55°C+155°C; Tolerance: 5%; Voltage: NA; Wattage: 1/16W; Weight: 0.65mg; Datasheet: Y:\MIS_DATABASE\DATASHEETS\RESISTORS\RCXXXXL-SER_MAR18.PDF
R183 = RESISTOR: RES 0E 1/10W JUMPER 0402; Chkd/date: VASANTHA/061216; Crtd /date: NAVEED/201014; Custom_Duty: 15%; Customs_HS_Code: 85332119; Distributor_name: DIGIKEY; Distributor_part_number: P0.0JCT-ND; Footprint Path: Y:\MIS_DATABASE\Library\ALTIUM_TOOL\PCB_FOOTPRINTS\Altium_Footprint_Lib.PcbLib; Footprint Ref: r402-25; Height: 0.40MM; IBISSP_MODLES: VALUE REPEATING 2 TIME; Library Path: Y:\MIS_DATABASE\Library\ALTIUM_TOOL\SCHEMATICS_PARTS\MS_DISCRETE_Library.schlib; MECHANICAL 3D STEP FILE: r402-25; Mfr_name: PANASONIC-ECG; Mfr_part_number: ERJ-2GE0R00X; Mistral Part No: 110018030052-R; Package: 0402; Part #: 102145-1003R; Part_type: RESISTORS\FIXED; Project: AEGIS POM; RoHS: RoHS; Temperature: -55°C+155°C; Tolerance: NA; Voltage: NA; Wattage: 1/10W; Weight: 0.8mg; Datasheet: Y:\MIS_DATABASE\DATASHEETS\RESISTORS\PAN-ERJSER_NOV17.PDF
R293 = RES_0402_10k_1.0%_0.063W_X: Part #: 102145-1003R
RJ3 = RJUMP3: Part #: 102145-1003R
RJ17 = RJUMP3B: Part #: 101370-0001R
SW1 = SW_DIP-2_0: Part #: 101184-0002R
TP23 TP34 = TP_VIA_MEM0_0: Part #: TP-18RD8-NO-POP
U24 = MOSFET-SIS434DN: IC MOSFET N-CHANNEL 30V 127A SO-8FL(DFN5); Chkd/date: VASANTHA/010419; Crtd /date: ALVY/010419; Custom_Duty: 15%; Customs_HS_Code: 85423100; Distributor_name: DIGIKEY; Distributor_part_number: NVMFS4C05NT1GOSCT-ND; Footprint Path: Y:\MIS_DATABASE\Library\ALTIUM_TOOL\PCB_FOOTPRINTS\Altium_Footprint_Lib.PcbLib; Height: 1.10MM; Library Path: Y:\MIS_DATABASE\Library\ALTIUM_TOOL\SCHEMATICS_PARTS\MS_MOSFET_Library.schlib; Mfr_name: ON SEMICONDUCTOR; Mistral Part No: 142019040001-R; Package: SO-8FL; Part #: 105367-0001R; Part_type: ICS\POWER\MOSFET; Project: J7ES_SOM_DUAL-LEO_PMIC; RoHS: RoHS; Temperature: -55°C+175°C; Tolerance: NA; Voltage: NA; Wattage: NA; Weight: NA; Datasheet: Y:\MIS_DATABASE\DATASHEETS\ICS\POWER\NVMFS4C05N.PDF
U27 = TPS65941-Q1_VQFN56_0: IC POWER MANAGEMENT WITH 4-PHASE 14A BUCK VQFN56; Chkd/date: VASANTHA/030419; Crtd /date: ALVY/070319; Custom_Duty: 15%; Customs_HS_Code: 85423100; Distributor_name: NA; Distributor_part_number: NA; Footprint Path: Y:\MIS_DATABASE\Library\ALTIUM_TOOL\PCB_FOOTPRINTS\Altium_Footprint_Lib.PcbLib; Height: 0.90MM; Library Path: Y:\MIS_DATABASE\Library\ALTIUM_TOOL\SCHEMATICS_PARTS\MS_MISCPOWER_Library.schlib; Library Ref: TPS65941-Q1_VQFN56; Mfr_name: TEXAS INSTRUMENTS; Mistral Part No: 142019030001-R; Package: VQFN56; Part #: 105327-0001R-TI; Part_type: ICS\POWER\MANAGEMENT; Project: J7ES_SOM_DUAL-LEO_PMIC; RoHS: RoHS; Temperature: -40°C+125°C; Tolerance: NA; Voltage: NA; Wattage: NA; Weight: NA; Datasheet: Y:\MIS_DATABASE\DATASHEETS\ICS\POWER\TPS65941-Q1.PDF
U77 = SN74LVC1G08DCK: Part #: 105368-0008R
Y8 = CRY: CRY 32.768KHz 9pF SMD; Chkd/date: VASANTHA/090419; Crtd /date: ALVY/090419; Custom_Duty: 24%; Customs_HS_Code: 85439000; Distributor_name: DIGIKEY; Distributor_part_number: XC2160CT-ND; Footprint Path: Y:\MIS_DATABASE\Library\ALTIUM_TOOL\PCB_FOOTPRINTS\Altium_Footprint_Lib.PcbLib; Height: 0.90MM; Library Path: Y:\MIS_DATABASE\Library\ALTIUM_TOOL\SCHEMATICS_PARTS\MS_DISCRETE_Library.schlib; Mfr_name: ECS INC; Mfr_part_number: ECS-.327-9-34QCS-TR; Mistral Part No: 130019040003-R; Package: SMD; Part #: 105332-3276R; Part_type: CRYSTAL; Project: J7ES_SOM_DUAL-LEO_PMIC; RoHS: RoHS; Temperature: -40°C+125°C; Tolerance: NA; Voltage: NA; Wattage: NA; Weight: 16mg; Datasheet: Y:\MIS_DATABASE\DATASHEETS\MISC\CRY_OSC\ECS-34Q.PDF

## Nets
DGND: C19.2 C20.2 C41.1 C42.1 C43.2 C47.1 C56.2 C119.2 C135.2 C136.2 C137.2 C138.2 C139.2 C140.2 C151.2 C152.2 C157.2 C158.2 C175.2 C176.2 C179.2 C180.2 C201.2 C223.1 C224.2 C225.1 C229.2 C230.2 C239.1 C243.1 C249.1 C251.2 C266.2 C274.2 C278.2 C279.2 C280.2 C298.2 C310.2 C313.1 C320.1 C340.2 C341.2 C343.2 C344.2 C350.2 C353.2 C357.1 C358.2 C364.2 C376.2 C377.2 C403.2 C404.2 C439.2 C448.2 C492.2 C547.2 C548.2 C552.2 C554.2 C555.2 C556.2 C557.2 C558.2 C563.2 C564.2 C568.2 C572.2 C573.2 C576.2 C577.2 C578.2 C582.2 C592.1 C593.1 C607.2 C645.2 C646.2 C647.2 C648.2 C681.2 C713.2 C754.2 C837.1 C839.1 D6.2(ANODE) D7.2(ANODE) D9.2(ANODE) D25.1(CATHODE) DS1.1(cathode) J14.2 J17.2 Q2.1(S2) Q2.4(S2) Q10.1(S) Q11.1(S) R25.2 R104.2 R106.1 R107.1 R108.1 R111.2 R123.1 R159.2 R175.1 R180.2 R182.2 R183.1 R184.2 R189.2 R270.2 R291.1 RJ3.3 SW1.3(B2) TP52.1 TP78.1 TP79.1 TP80.1 TP81.1 TP82.1 TP83.1 TP84.1 U8.10(AGND) U8.15(PGND) U8.16(PGND) U8.17(TPAD) U27.5(REFGND1) U27.6(REFGND2) U27.21(FB_B2) U27.36(VBACKUP) U27.57(GND) U33.3(AGND) U33.9(PGND) U33.25(DAP) U38.3(GND) U46.10(AGND) U46.13(ISNS(-)) U46.14(ISNS(+)) U46.22(PGND) U46.29(PAD) U64.2(GND) U77.3(GND) ; also on sheet 8 9 10 11 12 13 14 15 17 18 19 20 24 25 26 27 28 29 30 31 32 33 34 35 36 37 38 39 40
PVDD: C376.1 C448.1 L49.2 TP65.1(TP) ; also on sheet 32
VBAT: C477.2 C838.2 D26.1(CATHODE) J17.1 Q9.1(S1) Q9.2(S2) Q9.3(S3) U64.3(EN) U64.6(ANODE)
VBAT_SYS: C266.1 C358.1 C364.1 C377.1 C439.1 C645.1 C646.1 C647.1 C648.1 D13.2(ANODE) J14.1 L46.2 Q7.5(D) Q12.5(D) Q13.5(D) R199.1 R315.2 R342.2 TP60.1(TP) U33.15(VIN) ; also on sheet 37
VCC_LM5141: C230.1 D8.2(ANODE) U33.10(VCC)
VCC_LM5175: C350.1 D11.2(A) D12.2(A) R193.2 U46.23(VCC)
VCCA_3V3: C119.1 C157.1 C158.1 C175.1 C176.1 C201.1 C547.1 C548.1 C552.1 C556.1 C557.1 C558.1 C563.1 C564.1 C572.1 C573.1 U24.1(S1) U24.2(S2) U24.3(S3) U27.4(VCCA) U27.8(PVIN_LDO4) U27.10(PVIN_LDO3) U27.12(PVIN_LDO12) U27.17(PVIN_B2) U27.26(PVIN_B1) U27.35(PVIN_B5) U27.45(PVIN_B3) U27.54(PVIN_B4) ; also on sheet 24 25
VDD1_LPDDR4_1V8: C135.1 U27.13(VOUT_LDO1) ; also on sheet 11
VDD_CPU_AVS: C151.1 C179.1 C554.1 C577.1 L32.2 L36.2 U27.22(FB_B1) ; also on sheet 19
VDD_CPU_AVS_REG_SW1: L36.1 U27.27(SW_B1A) U27.28(SW_B1B)
VDD_CPU_AVS_REG_SW2: L32.1 U27.15(SW_B2A) U27.16(SW_B2B)
VDD_DDR_1V1: C152.1 C555.1 L33.2 U27.50(FB_B4) ; also on sheet 11 19 24
VDD_DDR_1V1_REG_SW: L33.1 U27.55(SW_B4A) U27.56(SW_B4B)
VDD_IO_3V3: R164.1 ; also on sheet 10 15 16 18 25 26 27 28 29 30 31 32 34 35 36 37 38 39 40
VDD_MCU_0V85: C180.1 C576.1 L37.2 U27.49(FB_B3) ; also on sheet 17 19
VDD_MCU_0V85_REG_SW: L37.1 U27.43(SW_B3A) U27.44(SW_B3B)
VDD_MCUIO_1V8: C136.1 U27.11(VOUT_LDO2) ; also on sheet 12 18
VDD_MCUIO_3V3: C568.1 C839.2 R284.2 R463.2 RJ3.1 U27.48(VIO_IN) U77.5(VCC) ; also on sheet 14 18 24 25 26 34 37 39
VDD_PHYIO_1V8: C229.1 C582.1 L38.2 U27.37(FB_B5) ; also on sheet 17
VDD_PHYIO_1V8_REG_SW: L38.1 U27.34(SW_B5A)
VDDA_LM5141: C224.1 R299.2 R300.2 R308.2 U33.2(VDDA)
VINT_LEOA_1V8: C140.1 U27.2(VOUT_LDOVINT) ; also on sheet 24
CAN_POWER_ON_HV: Q2.2(G2) ; also on sheet 37
CAN_WKUP: R293.1 SW1.1(A1) SW1.2(A2) TP23.1 U27.47(GPIO4)
CS_P: C769.1 Q4.1(S) Q5.1(S) R160.2 R180.1
EN_3V3IO_LDSW: U46.1(EN/UVLO) ; also on sheet 24 25 34 40
EN_DRV_OUT: TP34.1 U27.29(EN_DRV)
EN_MCU3V3IO_LDSW: R294.1 ; also on sheet 25
FB: R167.1 R175.2 U46.11(FB)
FB_5141: R123.2 R124.1 U33.19(FB)
H_MCU_INT#: R284.1 U27.14(nINT) ; also on sheet 14 24
H_MCU_PORz_1V8: R381.1 U27.25(nRSTOUT) ; also on sheet 12 14
H_MCU_SAFETY_ERRZ: U77.2(A) ; also on sheet 14
H_PMIC_POWER_EN1: RJ17.3 ; also on sheet 14
H_SOC_PORz_1V8: R290.1 U27.53(GPIO11) ; also on sheet 14
HDRV1_N: C361.2 L43.1 Q5.5(D) Q7.1(S) U46.28(SW1)
HDRV1_P: R202.2 U46.27(HDRV1)
HDRV2_N: C333.1 D9.1(CATHODE) D10.2(ANODE) L43.2 Q3.1(S) Q4.5(D) U46.18(SW2)
HDRV2_P: R150.1 U46.19(HDRV2)
LDRV1: R173.2 U46.25(LDRV1)
LDRV2: R172.1 U46.21(LDRV2)
LEOA_GPIO3: R294.2 U27.46(GPIO3)
LEOA_GPIO7: U27.18(GPIO7) U77.4(Y)
LEOA_GPIO8: R105.2 U27.41(GPIO8)
LEOA_GPIO9: R291.2 U27.19(GPIO9)
LEOA_GPIO10: R183.2 RJ17.2 U27.42(GPIO10)
LEOA_OSC32KCAP: C578.1 U27.40(OSC32KCAP)
LEOA_OSC32KIN: C593.2 U27.38(OSC32KIN) Y8.2
LEOA_OSC32KOUT: C592.2 U27.39(OSC32KOUT) Y8.1
LEOA_SCLK: U27.23(GPIO5) ; also on sheet 24
LEOA_SDATA: U27.24(GPIO6) ; also on sheet 24
LEOA_WDOG_DISABLE: R105.1 RJ3.2
LM5141_CS: C262.2 R129.1 R133.2 U33.18(CS)
LM5141_HB: C263.2 D8.1(CATHODE) U33.11(HB)
LM5141_HO: R326.2 U33.13(HO)
LM5141_HOL: R327.1 U33.14(HOL)
LM5141_LO: R310.2 U33.8(LO)
LM5141_LOL: R309.1 U33.7(LOL)
LM5141_SW: C226.2 C263.1 D7.1(CATHODE) L39.1 Q10.5(D) Q11.5(D) Q12.1(S) Q13.1(S) R133.1 U33.12(SW)
LM5141_VOUT: C262.1 R127.1 R129.2 U33.17(VOUT)
MCU_DMTIMER2: U38.2(I) ; also on sheet 13
MCU_DMTIMER3: C64.2 ; also on sheet 13
MCU_DMTIMER4: C354.1 ; also on sheet 13
MCU_DMTIMER8: RJ17.1 ; also on sheet 14
MCU_I2C0_SCL: U27.32(GPIO1) ; also on sheet 14
MCU_I2C0_SDA: U27.33(GPIO2) ; also on sheet 14
MCUBOOT_BUFF_ENz: U38.1(OE) ; also on sheet 14 34 39
PG_LM5141: R72.2 R323.1 TP33.1(TP) U33.21(PG) ; also on sheet 40
PG_LM5175: C313.2 R164.2 R271.1 TP53.1(TP) U46.17(PGOOD)
PG_LM53603: TP7.1(TP) U8.8(RESETn) ; also on sheet 28
SOC_PWR_EN: R72.1 U27.20(nPWRON/ENABLE)
SOC_SAFETY_ERRz: R463.1 U77.1(B) ; also on sheet 14
SOC_WKUP_I2C0_SCL: U27.31(SCL_I2C1/SCK_SPI) ; also on sheet 14 24
SOC_WKUP_I2C0_SDA: U27.30(SDA_I2C1/SDI_SPI) ; also on sheet 14 24
USB0_CS: C499.1 R268.2 R272.1 ; also on sheet 28
VDA_DLL_0V8: C137.1 U27.9(VOUT_LDO3) ; also on sheet 17
VDA_MCU_1V8: C138.1 R290.2 R381.2 U27.7(VOUT_LDO4) ; also on sheet 17
VOSNS: C320.2 R168.2 U46.12(VOSNS)
VRTC_LEOA_1V8: C139.1 R293.2 U27.3(VOUT_LDOVRTC)
VSYS_3V3: C274.1 C278.1 C279.1 C280.1 C681.1 L39.2 R98.1 R125.2 R127.2 R323.2 U24.5(D) U38.5(VCC) ; also on sheet 17 25 34 40
VSYS_5V0: C607.1 U33.16(VCCX) ; also on sheet 37 39 40
VSYS_10V5: U46.24(BIAS) ; also on sheet 40
VSYS_16V0: C41.2 C42.2 C43.1 C298.1 C310.1 C713.1 C754.1 C769.2 Q3.5(D) R153.2 R168.1 TP44.1(TP) U8.12(VIN1) U8.13(VIN2) ; also on sheet 40
VSYS_SENSE: D6.1(CATHODE) R99.2 U27.51(VSYS_SENSE)
VUSB_5V0: C19.1 C20.1 C499.2 L4.2 R267.2 R268.1 TP3.1(TP) ; also on sheet 28
N27191474: R83.2 U27.52(OVPGDRV)
N27191486: R83.1 U24.4(GATE)
N27191539: R98.2 R99.1
N29427544: C403.1 C404.1 L46.1 L49.1 Q9.5(D1) R260.2 U64.4(CATHODE)
N29427613: C837.2 C838.1
N29427634: D25.2(ANODE) D26.2(ANODE)
N29427748: DS1.2(ANODE) R260.1
N29427750: Q9.4(G) U64.5(GATE)
N29427801: C477.1 U64.1(VCAP)
N30188271: Q12.4(G) Q13.4(G) R326.1 R327.2
N30188608: Q10.4(G) Q11.4(G) R309.2 R310.1
N31193882: Q7.4(G) R202.1
N31194203: Q5.4(G) R173.1
N31194290: Q4.4(G) R172.2
N31194295: Q3.4(G) R150.2
N31194655: D13.1(CATHODE) R198.1
N31194670: C353.1 R198.2 U46.2(VIN)
N31194787: C361.1 D12.1(K) U46.26(BOOT1)
N31194818: C333.2 D10.1(CATHODE) D11.1(K) U46.20(BOOT2)
N31196095: C315.2 R159.1 U46.15(CSG)
N31196104: C315.1 R160.1 U46.16(CS)
N31196146: C344.1 U46.7(SLOPE)
N31196169: R184.1 U46.5(DTH)
N31196187: C354.2 R182.1 U46.6(RT/SYNC)
N31196205: R189.1 R193.1 U46.4(MODE)
N31196259: C341.1 R181.2 U46.9(COMP)
N31196266: C343.1 R181.1
N31197066: C340.1 U46.8(SS)
N31197134: C357.2 R199.2 U46.3(VISNS)
N31197473: R153.1 R167.2 TP45.1(TP)
N31208960: C226.1 R104.1
N31222024: R108.2 R308.1 U33.1(DEMB) U38.4(O)
N31222073: C239.2 R111.1 R315.1 U33.23(EN)
N31222132: C249.2 R117.1
N31222198: C251.1 R117.2 U33.20(COMP)
N31222241: C225.2 U33.24(RES)
N31222246: C243.2 U33.22(SS)
N31222265: R106.2 R300.1 U33.6(OSC)
N31222285: C223.2 R299.1 U33.5(DITH)
N31222303: R107.2 U33.4(RT)
N31222717: R124.2 R125.1
N31223527: L4.1 R12.2 R262.1 R263.1 U8.1(SW1) U8.2(SW2)
N31223584: C56.1 R267.1 U8.5(BIAS)
N31223889: C33.2 R12.1
N31224124: R270.1 R272.2 U8.9(FB)
N31225630: R271.2 U8.11(EN)
N31225660: C64.1 R25.1 U8.6(SYNC)
N31226612: C47.2 U8.4(VCC) U8.7(FPWM)
N31555915: C492.1 R262.2 R263.2
N32140279: Q2.3(D2) SW1.4(B1)
N32140322: Q2.5(G2) Q2.6(D2) R342.1
N33182650: C33.1 U8.3(CBOOT)

Not connected (* = marked no-connect by the designer): U8 14(NC)*; U27 1(AMUXOUT)*

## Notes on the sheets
sheet 21
- INPUT PROTECTION AND FILTER
- Vds  40V
  Vgs +-20V
  Vgs(TH) 2.0V
  RDSon 3.4mOHM@Vgs10v
  Id  75A
  Ciss 3730pF
  Vcap(min) 37nF
- DFEH12060D-3R3M=P3
- LCARD - CLASS-D, 12V@10A PEAK
- VBAT
  12v
- DFEG10040D-3R3M=P3
- LCARD - 16V BOOST@4A MAX
- 32Amp Per Contact
- LCARD - LM5141 3.3V@7A MAX
- 3.3uH/470uF - Fcutoff = 4.04KHz
- OPTIONAL FAN CONNECTOR
- STAGE-1 16V BOOST
- LCARD - 16V BOOST@4A MAX
- EEE-FKV121XSP
- REV-B
- 1.23V Vth
- 3.16K
- ~2ms delay
- 226KHz Fswitch default
sheet 22
- STAGE-1 3.3V AND 5 V POWER
- FOR 3.3v@15A
  L = SRP1265A-2R2 - DCR=3.8-4.2mOHM, Irms=22A, Isat=40A
  MQH/QL = BSZ034N04LS (lower Rdson, or no change)
  Cout 22uFx2 +  120uF EEE-FKV121XSP
  Cin 22uF x2 (10uFX4)
  Comp - 8.45K, 3.3nF, 68pf, Cross 55KHz, Phase Margin 51
  Current sense 5.49K (5.79K-5.24K)
- DEMB DEFAULTS TO 2.5V WHEN NOT DRIVEN.
- DITH DISABLE
- LCARD - LM5141 3.3V@7A MAX
- SRP1265A-2R2
- REV-B
- 2.0V Vth
- SINGLE POINT CONNECTION
- LCARD - USB2.0 - 500mA
- LCARD - USB3.0 - CDP: Charge + Data (2.1A)
- C(comp)
- R(fa)
- 2.0V Vth
- R(fb)
- R(g)
sheet 23
- "PCB Notes:
  For multi-phase Buck converter configs, route
  remote sense feedback as follows:
     1. Pseudo differential pair traces on same layer
  & next to primarily power plane segment. Avoid
  routing near to any noisy/switching signals.
     2. Connect each trace, as close as possible, to
  power & Gnd vias or across Dcap in middle of SOC
  power ball group.
     3. Trace widths = 4-8mil & separation distance =
  8-50mil, try to keep traces near each other as best
  as possible while
   For single-phase Buck converters, route remote
  sense feedback as follows:
     1. Single-ended traces on same layer & next to
  primarily power plane segment as best as possible.
  Avoid routing near to any noisy/switching signals.
     2. Connect each trace, as close as possible, to
  a power via near in middle of SOC power ball group.
     3. Trace widths = 4-8mil"
- PMIC- A
- Connect GPIO9 to Gnd per PMIC ES1
  "nSLEEP Deglitcher" errata work-around.
- PMIC-A uses default I2C ADDR:
  0x48, 0x49, 0x4A & 0x4B
- CAN_POWER_ON_HV HIGH == VBAT_SYS.
  CAN_POWER_ON_HV HAS 100K PULLDOWN AT
  CAN XCVR.
  CAN_POWER_ON_HV HAS 2 STATES - HIGH, Z,
  CANNOT PULL LOW.
